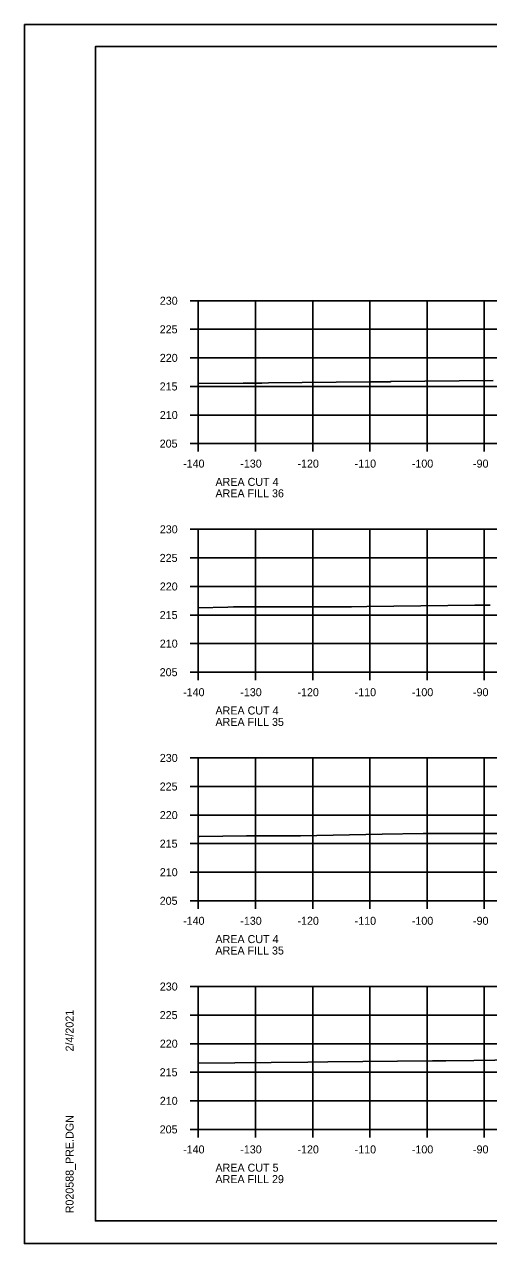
# Model space of a CAD drawing. Extents: x 1368968 to 1369915, y 377395 to 380381.
# Drawn here: x 1369581.4 to 1369662.5, y 379314.7 to 379528.1 of the extents above; entities that cross this region are included whole.
import ezdxf

# ---------------------------------------------------------------- set-up
doc = ezdxf.new("R2010")
doc.units = 0
for name, color, linetype in [('S_BREAKLINE_ANNOT', 7, 'Continuous'), ('S_BRIDGE', 7, 'Continuous'), ('S_BRIDGE_ANNOT', 7, 'Continuous'), ('S_CTL_TABLE', 7, 'Continuous'), ('S_DITCHLINE_ANNOT', 7, 'Continuous'), ('S_DROP_INLET', 7, 'Continuous')]:
    doc.layers.add(name, color=color, linetype=linetype)

msp = doc.modelspace()

# ---------------------------------------------------------------- linework, layer by layer
at = {"layer": 'S_BREAKLINE_ANNOT'}
for p, q in [((1369610.38, 379479.72), (1369611.78, 379479.72)), ((1369611.78, 379454.72), (1369611.78, 379479.72)), ((1369610.38, 379474.72), (1369611.78, 379474.72)), ((1369610.38, 379469.72), (1369611.78, 379469.72)), ((1369610.38, 379464.72), (1369611.78, 379464.72)), ((1369610.38, 379459.72), (1369611.78, 379459.72)), ((1369610.38, 379454.72), (1369611.78, 379454.72)), ((1369611.78, 379454.72), (1369891.78, 379454.72)), ((1369611.78, 379453.32), (1369611.78, 379454.72)), ((1369621.78, 379453.32), (1369621.78, 379454.72)), ((1369631.78, 379453.32), (1369631.78, 379454.72)), ((1369641.78, 379453.32), (1369641.78, 379454.72)), ((1369651.78, 379453.32), (1369651.78, 379454.72)), ((1369661.78, 379453.32), (1369661.78, 379454.72)), ((1369610.38, 379439.72), (1369611.78, 379439.72)), ((1369611.78, 379414.72), (1369611.78, 379439.72)), ((1369610.38, 379434.72), (1369611.78, 379434.72)), ((1369610.38, 379429.72), (1369611.78, 379429.72)), ((1369610.38, 379424.72), (1369611.78, 379424.72)), ((1369610.38, 379419.72), (1369611.78, 379419.72)), ((1369610.38, 379414.72), (1369611.78, 379414.72)), ((1369611.78, 379414.72), (1369891.78, 379414.72)), ((1369611.78, 379413.32), (1369611.78, 379414.72)), ((1369621.78, 379413.32), (1369621.78, 379414.72)), ((1369631.78, 379413.32), (1369631.78, 379414.72)), ((1369641.78, 379413.32), (1369641.78, 379414.72)), ((1369651.78, 379413.32), (1369651.78, 379414.72)), ((1369661.78, 379413.32), (1369661.78, 379414.72)), ((1369610.38, 379399.72), (1369611.78, 379399.72)), ((1369611.78, 379374.72), (1369611.78, 379399.72)), ((1369610.38, 379394.72), (1369611.78, 379394.72)), ((1369610.38, 379389.72), (1369611.78, 379389.72)), ((1369610.38, 379384.72), (1369611.78, 379384.72)), ((1369610.38, 379379.72), (1369611.78, 379379.72)), ((1369610.38, 379374.72), (1369611.78, 379374.72)), ((1369611.78, 379374.72), (1369891.78, 379374.72)), ((1369611.78, 379373.32), (1369611.78, 379374.72)), ((1369621.78, 379373.32), (1369621.78, 379374.72)), ((1369631.78, 379373.32), (1369631.78, 379374.72)), ((1369641.78, 379373.32), (1369641.78, 379374.72)), ((1369651.78, 379373.32), (1369651.78, 379374.72)), ((1369661.78, 379373.32), (1369661.78, 379374.72)), ((1369610.38, 379359.72), (1369611.78, 379359.72)), ((1369611.78, 379334.72), (1369611.78, 379359.72)), ((1369610.38, 379354.72), (1369611.78, 379354.72)), ((1369610.38, 379349.72), (1369611.78, 379349.72)), ((1369610.38, 379344.72), (1369611.78, 379344.72)), ((1369610.38, 379339.72), (1369611.78, 379339.72)), ((1369610.38, 379334.72), (1369611.78, 379334.72)), ((1369611.78, 379334.72), (1369891.78, 379334.72)), ((1369611.78, 379333.32), (1369611.78, 379334.72)), ((1369621.78, 379333.32), (1369621.78, 379334.72)), ((1369631.78, 379333.32), (1369631.78, 379334.72)), ((1369641.78, 379333.32), (1369641.78, 379334.72)), ((1369651.78, 379333.32), (1369651.78, 379334.72)), ((1369661.78, 379333.32), (1369661.78, 379334.72))]:
    msp.add_line(p, q, dxfattribs=at)
at = {"layer": 'S_BRIDGE_ANNOT'}
for p, q in [((1369593.78, 379524.18), (1369909.96, 379524.18)), ((1369593.78, 379318.72), (1369593.78, 379524.18)), ((1369593.78, 379318.72), (1369593.78, 379318.72)), ((1369909.96, 379318.72), (1369593.78, 379318.72))]:
    msp.add_line(p, q, dxfattribs=at)
at = {"layer": 'S_CTL_TABLE'}
for points in [[(1369611.78, 379465.24), (1369619.61, 379465.3), (1369622.9, 379465.32), (1369624.03, 379465.33), (1369641.8, 379465.5), (1369642.71, 379465.51), (1369643.4, 379465.51), (1369645.33, 379465.54), (1369645.43, 379465.57), (1369663.33, 379465.74)], [(1369611.78, 379425.98), (1369616.96, 379426.11), (1369617.95, 379426.13), (1369638.56, 379426.17), (1369641.27, 379426.22), (1369660.14, 379426.47), (1369662.84, 379426.47)], [(1369611.78, 379385.94), (1369611.94, 379385.95), (1369620.19, 379386.08), (1369629.67, 379386.1), (1369643.95, 379386.38), (1369651.11, 379386.48), (1369661.9, 379386.5), (1369675.16, 379386.52)], [(1369611.78, 379346.31), (1369630.94, 379346.48), (1369634.45, 379346.53), (1369652.75, 379346.69), (1369652.82, 379346.69), (1369655.04, 379346.69), (1369659.97, 379346.76), (1369667.29, 379346.89)]]:
    msp.add_lwpolyline(points, dxfattribs=at)
at = {"layer": 'S_DITCHLINE_ANNOT'}
for p, q in [((1369611.78, 379479.72), (1369891.78, 379479.72)), ((1369611.78, 379454.72), (1369611.78, 379479.72)), ((1369621.78, 379454.72), (1369621.78, 379479.72)), ((1369631.78, 379454.72), (1369631.78, 379479.72)), ((1369641.78, 379454.72), (1369641.78, 379479.72)), ((1369651.78, 379454.72), (1369651.78, 379479.72)), ((1369661.78, 379454.72), (1369661.78, 379479.72)), ((1369611.78, 379474.72), (1369891.78, 379474.72)), ((1369611.78, 379469.72), (1369891.78, 379469.72)), ((1369611.78, 379464.72), (1369891.78, 379464.72)), ((1369611.78, 379459.72), (1369891.78, 379459.72)), ((1369611.78, 379454.72), (1369891.78, 379454.72)), ((1369611.78, 379439.72), (1369891.78, 379439.72)), ((1369611.78, 379414.72), (1369611.78, 379439.72)), ((1369621.78, 379414.72), (1369621.78, 379439.72)), ((1369631.78, 379414.72), (1369631.78, 379439.72)), ((1369641.78, 379414.72), (1369641.78, 379439.72)), ((1369651.78, 379414.72), (1369651.78, 379439.72)), ((1369661.78, 379414.72), (1369661.78, 379439.72)), ((1369611.78, 379434.72), (1369891.78, 379434.72)), ((1369611.78, 379429.72), (1369891.78, 379429.72)), ((1369611.78, 379424.72), (1369891.78, 379424.72)), ((1369611.78, 379419.72), (1369891.78, 379419.72)), ((1369611.78, 379414.72), (1369891.78, 379414.72)), ((1369611.78, 379399.72), (1369891.78, 379399.72)), ((1369611.78, 379374.72), (1369611.78, 379399.72)), ((1369621.78, 379374.72), (1369621.78, 379399.72)), ((1369631.78, 379374.72), (1369631.78, 379399.72)), ((1369641.78, 379374.72), (1369641.78, 379399.72)), ((1369651.78, 379374.72), (1369651.78, 379399.72)), ((1369661.78, 379374.72), (1369661.78, 379399.72)), ((1369611.78, 379394.72), (1369891.78, 379394.72)), ((1369611.78, 379389.72), (1369891.78, 379389.72)), ((1369611.78, 379384.72), (1369891.78, 379384.72)), ((1369611.78, 379379.72), (1369891.78, 379379.72)), ((1369611.78, 379374.72), (1369891.78, 379374.72)), ((1369611.78, 379359.72), (1369891.78, 379359.72)), ((1369611.78, 379334.72), (1369611.78, 379359.72)), ((1369621.78, 379334.72), (1369621.78, 379359.72)), ((1369631.78, 379334.72), (1369631.78, 379359.72)), ((1369641.78, 379334.72), (1369641.78, 379359.72)), ((1369651.78, 379334.72), (1369651.78, 379359.72)), ((1369661.78, 379334.72), (1369661.78, 379359.72)), ((1369611.78, 379354.72), (1369891.78, 379354.72)), ((1369611.78, 379349.72), (1369891.78, 379349.72)), ((1369611.78, 379344.72), (1369891.78, 379344.72)), ((1369611.78, 379339.72), (1369891.78, 379339.72)), ((1369611.78, 379334.72), (1369891.78, 379334.72))]:
    msp.add_line(p, q, dxfattribs=at)
at = {"layer": 'S_DROP_INLET'}
for p, q in [((1369581.38, 379528.07), (1369914.71, 379528.07)), ((1369581.38, 379314.74), (1369914.71, 379314.74))]:
    msp.add_line(p, q, dxfattribs=at)
for points in [[(1369581.37, 379528.07), (1369914.71, 379528.07), (1369914.71, 379314.74), (1369581.37, 379314.74)], [(1369827.7, 379524.18), (1369827.7, 379514.3), (1369863.43, 379514.3), (1369863.43, 379511.38), (1369886.63, 379511.38), (1369886.63, 379487.05), (1369909.96, 379487.05), (1369909.96, 379318.72), (1369593.78, 379318.72), (1369593.78, 379524.18)]]:
    msp.add_lwpolyline(points, close=True, dxfattribs=at)

# ---------------------------------------------------------------- texts
at = {"layer": 'S_BRIDGE'}
for s, p in [('230', (1369605.05, 379479.02)), ('225', (1369605.03, 379474.02)), ('220', (1369605.05, 379469.02)), ('215', (1369605.03, 379464.02)), ('210', (1369605.05, 379459.02)), ('205', (1369605.03, 379454.02)), ('-140', (1369609.12, 379450.52)), ('-130', (1369619.12, 379450.52)), ('-120', (1369629.12, 379450.52)), ('-110', (1369639.12, 379450.52)), ('-100', (1369649.12, 379450.52)), ('-90', (1369659.82, 379450.52)), ('AREA CUT 4', (1369614.78, 379447.32)), ('AREA FILL 36', (1369614.78, 379445.32)), ('230', (1369605.05, 379439.02)), ('225', (1369605.03, 379434.02)), ('220', (1369605.05, 379429.02)), ('215', (1369605.03, 379424.02)), ('210', (1369605.05, 379419.02)), ('205', (1369605.03, 379414.02)), ('-140', (1369609.12, 379410.52)), ('-130', (1369619.12, 379410.52)), ('-120', (1369629.12, 379410.52)), ('-110', (1369639.12, 379410.52)), ('-100', (1369649.12, 379410.52)), ('-90', (1369659.82, 379410.52)), ('AREA CUT 4', (1369614.78, 379407.32)), ('AREA FILL 35', (1369614.78, 379405.32)), ('230', (1369605.05, 379399.02)), ('225', (1369605.03, 379394.02)), ('220', (1369605.05, 379389.02)), ('215', (1369605.03, 379384.02)), ('210', (1369605.05, 379379.02)), ('205', (1369605.03, 379374.02)), ('-140', (1369609.12, 379370.52)), ('-130', (1369619.12, 379370.52)), ('-120', (1369629.12, 379370.52)), ('-110', (1369639.12, 379370.52)), ('-100', (1369649.12, 379370.52)), ('-90', (1369659.82, 379370.52)), ('AREA CUT 4', (1369614.78, 379367.32)), ('AREA FILL 35', (1369614.78, 379365.32)), ('230', (1369605.05, 379359.02)), ('225', (1369605.03, 379354.02)), ('220', (1369605.05, 379349.02)), ('215', (1369605.03, 379344.02)), ('210', (1369605.05, 379339.02)), ('205', (1369605.03, 379334.02)), ('-140', (1369609.12, 379330.52)), ('-130', (1369619.12, 379330.52)), ('-120', (1369629.12, 379330.52)), ('-110', (1369639.12, 379330.52)), ('-100', (1369649.12, 379330.52)), ('-90', (1369659.82, 379330.52)), ('AREA CUT 5', (1369614.78, 379327.32)), ('AREA FILL 29', (1369614.78, 379325.32))]:
    msp.add_text(s, height=1.4, dxfattribs=at).set_placement(p)
at = {"layer": 'S_BRIDGE_ANNOT'}
for s, p in [('2/4/2021', (1369589.97, 379348.36)), ('R020588_PRE.DGN', (1369589.97, 379320.04))]:
    msp.add_text(s, height=1.4, rotation=90, dxfattribs=at).set_placement(p)

doc.saveas('drawing.dxf')
